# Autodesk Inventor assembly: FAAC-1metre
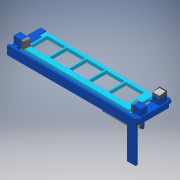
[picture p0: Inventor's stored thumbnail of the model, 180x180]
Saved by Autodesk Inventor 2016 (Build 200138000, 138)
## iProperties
Shininess: 41.0
Angle Display Precision: 2
Document Length Units: 11269
Document Angle Units: 11279
Document Time Units: 11290
Document Mass Units: 11283
Document Length Units Precision: 3
Document Angle Units Precision: 2
Created: 2002-09
Part Number: FAAC-1metre
Document SubType Name: Assemblage
Designer: administrateur
Density: 0.0
Volumn: 0.0
Area: 0.0
PropertySet Name: Model Information
Control State: 0
Master: False
Checked Out: False
Author: administrateur
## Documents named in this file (7)
- D:\Cours\1-Cours-2016-17\1Ssi\5. Statique\FAAC\Portail\FAAC-1metre.iam
- D:\Cours\1-Cours-2016-17\1Ssi\5. Statique\FAAC\Portail\Vérin.iam
- D:\Cours\1-Cours-2016-17\1Ssi\5. Statique\FAAC\Portail\Tige+piston.iam
- D:\Cours\1-Cours-2016-17\1Ssi\5. Statique\FAAC\Portail\Ecrou support arrière.ipt
- D:\Cours\1-Cours-2016-17\1Ssi\5. Statique\FAAC\Portail\Patte.ipt
- D:\Cours\1-Cours-2016-17\1Ssi\5. Statique\FAAC\Portail\Vantail 1metre.iam
- D:\Cours\1-Cours-2016-17\1Ssi\5. Statique\FAAC\Portail\Support 1metre-meca.iam
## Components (6 placed, 6 different names)
1. Vantail 1metre:1 [sub-assembly] — Plaquage:10, Placage:13, Placage:14
2. Vérin:1 [sub-assembly] — Plaquage:5, Plaquage:6, Placage:17
3. Ecrou support arrière:1 — Plaquage:12
4. Patte:1 — Plaquage:5, Plaquage:6, Plaquage:12, Placage:15, Placage:16
5. Tige+piston:1 [sub-assembly] — Plaquage:10, Placage:17
6. Support 1metre-meca:1 [sub-assembly] — Placage:13, Placage:14, Placage:15, Placage:16
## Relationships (9: Mate 9)
- Plaquage:5 [Mate]: Vérin:1 ↔ Patte:1
- Plaquage:6 [Mate]: Vérin:1 ↔ Patte:1
- Plaquage:10 [Mate]: Vantail 1metre:1 ↔ Tige+piston:1
- Plaquage:12 [Mate]: Ecrou support arrière:1 ↔ Patte:1
- Placage:13 [Mate]: Vantail 1metre:1 ↔ Support 1metre-meca:1
- Placage:14 [Mate]: Vantail 1metre:1 ↔ Support 1metre-meca:1
- Placage:15 [Mate]: Patte:1 ↔ Support 1metre-meca:1
- Placage:16 [Mate]: Patte:1 ↔ Support 1metre-meca:1
- Placage:17 [Mate]: Vérin:1 ↔ Tige+piston:1
